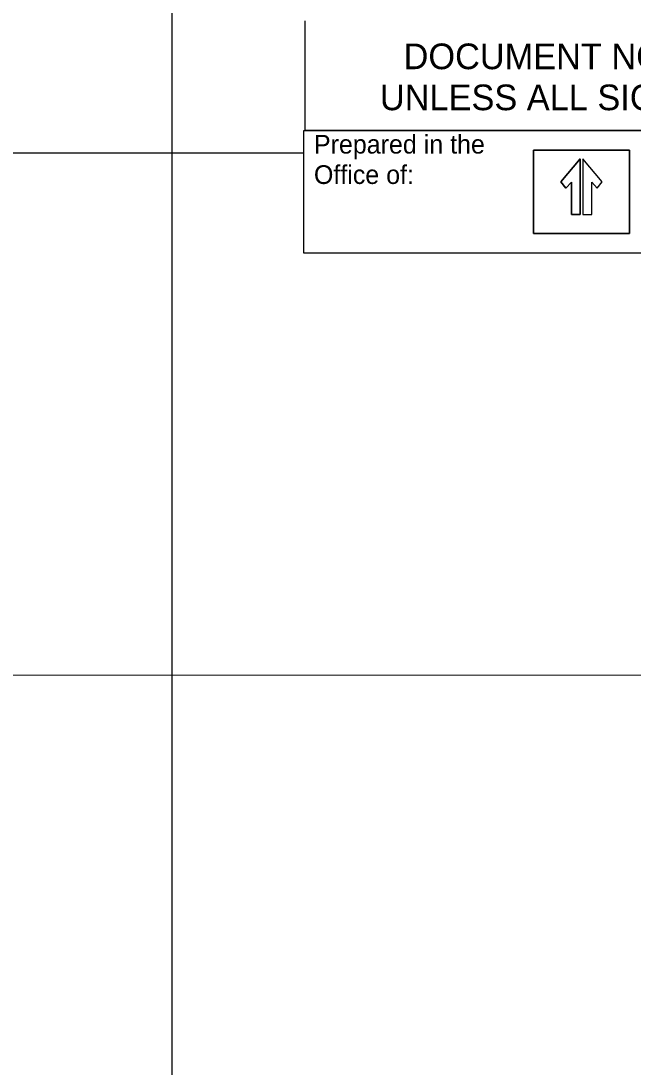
# Model space of a CAD drawing. Extents: x 1977705 to 1981198, y 827296 to 829291.
# Drawn here: x 1980758 to 1980880.5, y 828320.6 to 828530 of the extents above; entities that cross this region are included whole.
import ezdxf

# ---------------------------------------------------------------- set-up
doc = ezdxf.new("R2010")
doc.units = 0
for name, color, linetype in [('Level 12', 7, 'Continuous'), ('Level 13', 7, 'Continuous'), ('Level 34', 7, 'Continuous'), ('Level 7', 7, 'Continuous')]:
    doc.layers.add(name, color=color, linetype=linetype)

msp = doc.modelspace()

# ---------------------------------------------------------------- linework, layer by layer
at = {"layer": 'Level 12'}
for points in [[(1980814.64, 828508.05), (1981001.67, 828508.05), (1981001.67, 828483.5), (1980814.64, 828483.5)], [(1980860.55, 828504.12), (1980879.77, 828504.12), (1980879.77, 828487.44), (1980860.55, 828487.44)], [(1980870.44, 828502.41), (1980870.44, 828491.26), (1980872.2, 828491.26), (1980872.2, 828497.69), (1980873.28, 828496.54), (1980874.31, 828497.76)]]:
    msp.add_lwpolyline(points, close=True, dxfattribs=at)
for points in [[(1980879.77, 828504.12), (1980860.55, 828504.12), (1980860.55, 828487.44), (1980879.77, 828487.44), (1980879.77, 828504.12)], [(1980869.9, 828502.41), (1980869.9, 828491.26), (1980868.14, 828491.26), (1980868.14, 828497.69), (1980867.05, 828496.54), (1980866.03, 828497.76), (1980869.9, 828502.41)], [(1980866.03, 828497.76), (1980867.05, 828496.54), (1980868.14, 828497.69), (1980868.14, 828491.26), (1980869.9, 828491.26), (1980869.9, 828502.41), (1980866.03, 828497.76)], [(1980870.44, 828502.41), (1980870.44, 828491.26), (1980872.2, 828491.26), (1980872.2, 828497.69), (1980873.28, 828496.54), (1980874.31, 828497.76), (1980870.44, 828502.41)]]:
    msp.add_lwpolyline(points, dxfattribs=at)
at = {"layer": 'Level 13'}
for p, q in [((1980814.89, 828508.05), (1980814.89, 828529.99)), ((1981001.67, 828508.05), (1980814.89, 828508.05))]:
    msp.add_line(p, q, dxfattribs=at)
at = {"layer": 'Level 34'}
msp.add_line((1981001.97, 828399.12), (1979481.32, 828398.3), dxfattribs=at)
at = {"layer": 'Level 7'}
for points in [[(1980788.19, 828714.25), (1980788.19, 827737.43)], [(1979502.24, 828503.56), (1980814.64, 828503.56)]]:
    msp.add_lwpolyline(points, dxfattribs=at)

# ---------------------------------------------------------------- texts
at = {"layer": 'Level 12'}
for s, height, p in [('Prepared in the ', 3.7405, (1980816.63, 828503.44)), ('Office of:', 3.741, (1980816.63, 828497.36))]:
    msp.add_text(s, height=height, rotation=360, dxfattribs=at).set_placement(p)
at = {"layer": 'Level 13'}
for s, p in [('DOCUMENT NOT CONSIDERED FINAL', (1980834.57, 828520.33)), ('UNLESS ALL SIGNATURES COMPLETED', (1980829.83, 828512.12))]:
    msp.add_text(s, height=5.1354, dxfattribs=at).set_placement(p)

doc.saveas('drawing.dxf')
